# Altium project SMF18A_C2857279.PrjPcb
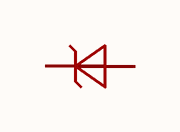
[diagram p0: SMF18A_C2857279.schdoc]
1 sheet, 1 parts. Net scope: global (net labels, ports and power ports of the same name join across sheets).

## Sheet SMF18A_C2857279.schdoc
size 127 x 101 mm

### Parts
D?  smf18a_c2857279  [SOD-123FL_L2.7-W1.8-LS3.7-RD]  (value not drawn)

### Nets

Not connected (* = marked no-connect by the designer): D? 1 2

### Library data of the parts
D? = smf18a_c2857279: 极性:单向;反向截止电压(Vrwm):18V;钳位电压:29.2V;峰值脉冲电流(Ipp):6.8A;峰值脉冲功率(Ppp):200W@10/1000us;击穿电压(VBR):20V;; Manufacturer: JSMSEMI(杰盛微); ManufacturerPart: SMF18A; AddInBom: yes; ModelId: 86f9151e155e4fe2af0c4f2e0a80302e; ModelName: SOD-123FL_L2.8-W1.8-H1.1-LS3.6; ModelTransform: 141.732,70.866,0,180,0,0,0,0,0; Polarity: 单向; Reverse Stand-Off Voltage (Vrwm): 18V; Clamping Voltage: 29.2V; Peak Pulse Current (Ipp): 6.8A; Voltage - Breakdown: 20V; Reverse Leakage Current (Ir): 1uA; Number of Channels: 单路; Type: TVS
